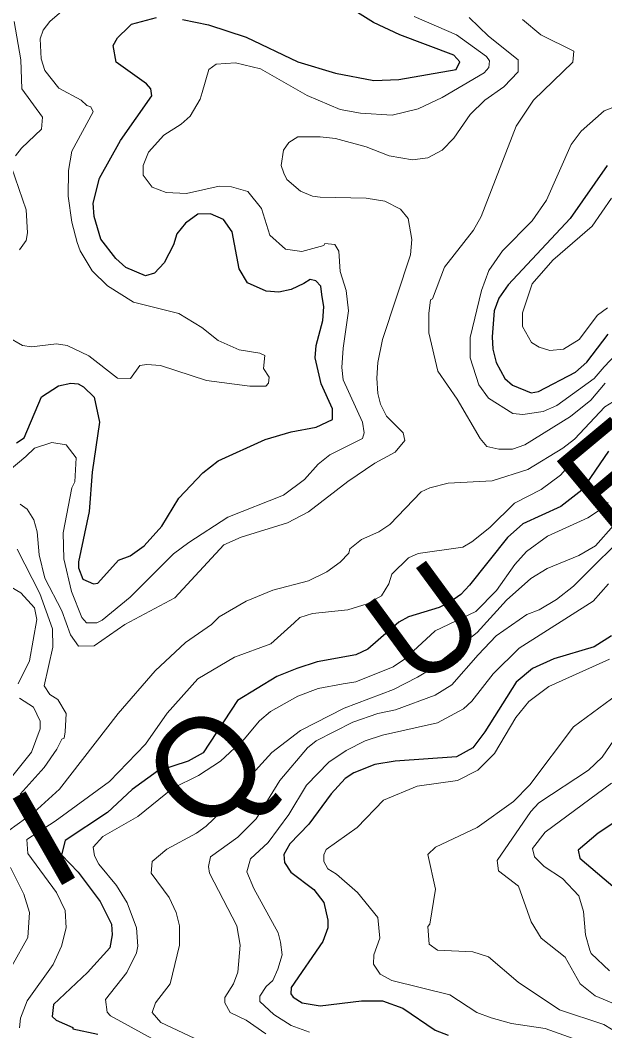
# Model space of a CAD drawing. Extents: x 423 to 448.8, y 7456.3 to 7484.
# Drawn here: x 431.771 to 432.712, y 7469.783 to 7471.409 of the extents above; entities that cross this region are included whole.
import ezdxf
from ezdxf.enums import TextEntityAlignment as Align

# ---------------------------------------------------------------- set-up
doc = ezdxf.new("R2010")
doc.units = 0
doc.header["$LTSCALE"] = 0.032
doc.layers.add('1', color=7, linetype='Continuous', lineweight=25)
doc.layers.add('2', color=7, linetype='Continuous', lineweight=13)
doc.layers.add('61', color=7, linetype='Continuous')

msp = doc.modelspace()

# ---------------------------------------------------------------- linework, layer by layer
at = {"layer": '1'}
for points in [[(432.0325, 7471.4102), (432.0743, 7471.4017), (432.1346, 7471.3815), (432.2181, 7471.3421), (432.2785, 7471.3236), (432.3404, 7471.3119), (432.3806, 7471.3135), (432.4726, 7471.3297), (432.4788, 7471.3421), (432.4687, 7471.3529), (432.3821, 7471.3854), (432.3396, 7471.4055), (432.3009, 7471.4295)], [(431.7657, 7470.7288), (431.778, 7470.7372), (431.8059, 7470.803), (431.833, 7470.8208), (431.8531, 7470.8247), (431.8646, 7470.8239), (431.8732, 7470.8193), (431.8902, 7470.8022), (431.8987, 7470.762), (431.8871, 7470.6816), (431.8825, 7470.6182), (431.8654, 7470.5377), (431.8654, 7470.5277), (431.8724, 7470.5098), (431.8894, 7470.5021), (431.8963, 7470.5029), (431.9296, 7470.54), (431.9482, 7470.547), (431.9706, 7470.5632), (431.9992, 7470.595), (432.0263, 7470.6398), (432.065, 7470.6808), (432.0897, 7470.7002), (432.1656, 7470.7342), (432.2073, 7470.7466), (432.2475, 7470.7543), (432.2738, 7470.7666), (432.2738, 7470.7837), (432.2553, 7470.8239), (432.246, 7470.8657), (432.2475, 7470.8858), (432.2584, 7470.926), (432.2599, 7470.9477), (432.2568, 7470.9678), (432.2552, 7470.9808), (432.2471, 7470.9896), (432.238, 7470.9917), (432.2274, 7470.9855), (432.2073, 7470.9755), (432.1872, 7470.9716), (432.1671, 7470.9732), (432.1369, 7470.9863), (432.1238, 7471.0088), (432.1121, 7471.0683), (432.0982, 7471.0884), (432.0774, 7471.0977), (432.0573, 7471.0969), (432.0372, 7471.0822), (432.0232, 7471.0652), (432.0178, 7471.0474), (432.0031, 7471.0188), (431.9876, 7471.0018), (431.9729, 7470.9979), (431.9412, 7471.0111), (431.925, 7471.0258), (431.901, 7471.0567), (431.8902, 7471.0931), (431.8886, 7471.1147), (431.8987, 7471.155), (431.9327, 7471.2153), (431.983, 7471.2872), (431.9815, 7471.2988), (431.9745, 7471.3066), (431.9257, 7471.3413), (431.9211, 7471.3684), (431.9281, 7471.3808), (431.9459, 7471.3986), (431.9505, 7471.4024), (431.9908, 7471.4133)], [(432.7155, 7471.175), (432.6559, 7471.0899), (432.5561, 7470.9832), (432.5414, 7470.9616), (432.5337, 7470.9415), (432.5306, 7470.8997), (432.5314, 7470.8796), (432.5368, 7470.858), (432.5507, 7470.8324), (432.5631, 7470.8216), (432.5933, 7470.8092), (432.6049, 7470.8115), (432.6644, 7470.8424), (432.683, 7470.8587), (432.717, 7470.9036)], [(432.7178, 7470.7156), (432.6745, 7470.653), (432.6412, 7470.6267), (432.5801, 7470.5988), (432.5553, 7470.5764), (432.4942, 7470.4998), (432.4803, 7470.4851), (432.4626, 7470.4728), (432.4455, 7470.4642), (432.396, 7470.4488), (432.3806, 7470.4402), (432.3303, 7470.397), (432.311, 7470.3877), (432.2491, 7470.3768), (432.2166, 7470.366), (432.1841, 7470.3528), (432.1207, 7470.3142), (432.0658, 7470.2299), (432.0418, 7470.2167), (431.9923, 7470.2005), (431.9513, 7470.1711), (431.9118, 7470.134), (431.8438, 7470.0891), (431.8376, 7470.0659), (431.8646, 7470.038), (431.9002, 7469.9909), (431.918, 7469.9545), (431.9196, 7469.9375), (431.9157, 7469.9166), (431.8794, 7469.8764), (431.8252, 7469.8254), (431.8229, 7469.806), (431.8291, 7469.7999), (431.8561, 7469.7882), (431.8561, 7469.7859), (431.8964, 7469.7774)], [(432.7224, 7470.4186), (432.6946, 7470.4008), (432.6296, 7470.3815), (432.5956, 7470.366), (432.5693, 7470.3436), (432.519, 7470.2639), (432.4997, 7470.2384), (432.4734, 7470.2237), (432.3744, 7470.2167), (432.3419, 7470.2113), (432.3079, 7470.1982), (432.2939, 7470.1889), (432.2715, 7470.1641), (432.2359, 7470.1154), (432.205, 7470.0837), (432.1957, 7470.0667), (432.1965, 7470.0536), (432.2065, 7470.038), (432.2437, 7470.0102), (432.2599, 7469.9893), (432.2661, 7469.9607), (432.2661, 7469.9483), (432.2584, 7469.9267), (432.2073, 7469.8524), (432.2065, 7469.8424), (432.2104, 7469.837), (432.2251, 7469.8277), (432.2537, 7469.823), (432.3202, 7469.8308), (432.3543, 7469.8308), (432.3868, 7469.8192), (432.4386, 7469.7836), (432.4595, 7469.7759)], [(432.7851, 7470.1564), (432.7008, 7470.1007), (432.6691, 7470.0736), (432.6714, 7470.0605), (432.7286, 7470.0125)]]:
    msp.add_lwpolyline(points, dxfattribs=at)
at = {"layer": '2'}
for points in [[(431.7509, 7470.8997), (431.7749, 7470.8858), (431.7897, 7470.8834), (431.8299, 7470.8881), (431.8469, 7470.8858), (431.8817, 7470.8687), (431.9281, 7470.8332), (431.949, 7470.8324), (431.9637, 7470.8533), (431.9753, 7470.8549), (431.9969, 7470.8533), (432.0712, 7470.8293), (432.1408, 7470.82), (432.1663, 7470.82), (432.1709, 7470.8247), (432.1717, 7470.8347), (432.1625, 7470.8486), (432.1648, 7470.8695), (432.157, 7470.8734), (432.1238, 7470.8788), (432.0898, 7470.8935), (432.0635, 7470.9144), (432.0263, 7470.9368), (431.9536, 7470.9554), (431.9119, 7470.9817), (431.8871, 7471.0057), (431.8677, 7471.0381), (431.8631, 7471.0513), (431.8546, 7471.0838), (431.8484, 7471.1256), (431.8492, 7471.1673), (431.8546, 7471.1983), (431.8886, 7471.2617), (431.8848, 7471.2694), (431.8786, 7471.2717), (431.8693, 7471.2803), (431.8337, 7471.2996), (431.8113, 7471.3282), (431.8051, 7471.3468), (431.8036, 7471.3793), (431.8082, 7471.3931), (431.819, 7471.4071), (431.8383, 7471.4233)], [(431.7711, 7470.6305), (431.7827, 7470.622), (431.7935, 7470.605), (431.7989, 7470.5857), (431.802, 7470.5486), (431.8113, 7470.5114), (431.8383, 7470.4588), (431.8523, 7470.4202), (431.8654, 7470.4016), (431.8902, 7470.4023), (431.9397, 7470.4364), (432.0201, 7470.4797), (432.099, 7470.5648), (432.1269, 7470.5772), (432.2011, 7470.6004), (432.2351, 7470.6181), (432.2985, 7470.6669), (432.3419, 7470.6963), (432.3744, 7470.714), (432.3899, 7470.7326), (432.3875, 7470.745), (432.3605, 7470.7721), (432.3511, 7470.7912), (432.3465, 7470.8084), (432.345, 7470.8332), (432.3465, 7470.858), (432.3543, 7470.8951), (432.3991, 7471.0312), (432.4014, 7471.056), (432.3952, 7471.0899), (432.3829, 7471.1047), (432.3581, 7471.1178), (432.328, 7471.1225), (432.2537, 7471.124), (432.2414, 7471.1256), (432.222, 7471.134), (432.2003, 7471.1526), (432.1957, 7471.1627), (432.191, 7471.1751), (432.1949, 7471.1998), (432.2034, 7471.2122), (432.2181, 7471.2215), (432.2537, 7471.2215), (432.2785, 7471.2184), (432.328, 7471.2052), (432.3651, 7471.1905), (432.4022, 7471.1843), (432.427, 7471.1874), (432.4501, 7471.1998), (432.4687, 7471.2191), (432.495, 7471.2571), (432.519, 7471.2803), (432.5492, 7471.3019), (432.5724, 7471.3259), (432.5724, 7471.3452), (432.5244, 7471.3831), (432.4935, 7471.4132)], [(432.0448, 7471.2547), (432.0611, 7471.2818), (432.0642, 7471.2926), (432.075, 7471.3298), (432.0867, 7471.3382), (432.1176, 7471.3406), (432.1578, 7471.3305), (432.2328, 7471.288), (432.2862, 7471.2655), (432.3187, 7471.2593), (432.3697, 7471.2563), (432.4115, 7471.2663), (432.4502, 7471.2849), (432.5175, 7471.3243), (432.5252, 7471.3328), (432.526, 7471.3437), (432.5213, 7471.3506), (432.4733, 7471.3854), (432.4053, 7471.4148)], [(431.7641, 7471.1905), (431.7734, 7471.2029), (431.8059, 7471.2338), (431.8074, 7471.2532), (431.7741, 7471.2988), (431.7726, 7471.3452), (431.7618, 7471.4071)], [(432.5793, 7471.4102), (432.6087, 7471.3854), (432.6621, 7471.3591), (432.6605, 7471.3413), (432.5971, 7471.2802), (432.5693, 7471.2385), (432.5128, 7471.0931), (432.5004, 7471.0714), (432.454, 7471.0118), (432.4347, 7470.9608), (432.4316, 7470.9592), (432.4285, 7470.9368), (432.4285, 7470.9059), (432.4432, 7470.844), (432.4742, 7470.7992)], [(432.7294, 7470.8711), (432.7108, 7470.851), (432.6946, 7470.8324), (432.6343, 7470.7891), (432.6126, 7470.7791), (432.5801, 7470.7744), (432.5639, 7470.7759), (432.5244, 7470.8007), (432.5089, 7470.8224), (432.495, 7470.8657), (432.495, 7470.8982), (432.5136, 7470.974), (432.5252, 7471.0065), (432.5469, 7471.0381), (432.5948, 7471.0861), (432.618, 7471.1193), (432.6574, 7471.2091), (432.6737, 7471.2307), (432.7108, 7471.2632), (432.7426, 7471.2756)], [(431.7502, 7470.6816), (431.7804, 7470.7071), (431.7942, 7470.7203), (431.8221, 7470.7295), (431.8453, 7470.7257), (431.8616, 7470.7048), (431.8593, 7470.6661), (431.8546, 7470.6568), (431.8407, 7470.5841), (431.8414, 7470.5424), (431.8538, 7470.4898), (431.8708, 7470.448), (431.8778, 7470.4395), (431.8948, 7470.4395), (431.9033, 7470.4434), (431.9482, 7470.4805), (432.0178, 7470.5501), (432.0426, 7470.5687), (432.1052, 7470.6096), (432.1949, 7470.6445), (432.2289, 7470.67), (432.2506, 7470.6947), (432.2692, 7470.7094), (432.3218, 7470.7357), (432.3249, 7470.745), (432.3218, 7470.762), (432.2908, 7470.8301), (432.2885, 7470.8502), (432.2908, 7470.8812), (432.2993, 7470.9415), (432.2955, 7470.974), (432.2862, 7471.0049), (432.2839, 7471.0374), (432.2777, 7471.0482), (432.2614, 7471.0497), (432.2599, 7471.0466), (432.2243, 7471.0366), (432.198, 7471.0404), (432.1732, 7471.0629), (432.1594, 7471.1062), (432.1377, 7471.1333), (432.1114, 7471.141), (432.0913, 7471.1418), (432.0387, 7471.1302), (432.0062, 7471.1317), (431.9838, 7471.1402), (431.9691, 7471.1596), (431.9691, 7471.1751), (431.9776, 7471.1967), (432.0023, 7471.2238), (432.0302, 7471.2415), (432.0448, 7471.2547)], [(431.7703, 7471.0397), (431.7811, 7471.0544), (431.7834, 7471.0668), (431.7811, 7471.1039), (431.7572, 7471.1727)], [(432.7224, 7471.1224), (432.6915, 7471.0776), (432.6281, 7471.0227), (432.5948, 7470.9848), (432.5793, 7470.9384), (432.5793, 7470.9159), (432.594, 7470.8904), (432.6064, 7470.8827), (432.6234, 7470.8773), (432.6451, 7470.8796), (432.6706, 7470.8951), (432.7, 7470.9345), (432.7163, 7470.9461)], [(432.4742, 7470.7992), (432.5113, 7470.7357), (432.5221, 7470.7233), (432.5415, 7470.7187), (432.5631, 7470.7187), (432.5832, 7470.7257), (432.6567, 7470.7713), (432.6892, 7470.7976), (432.7124, 7470.8247)], [(432.7395, 7470.8038), (432.7116, 7470.7868), (432.6629, 7470.735), (432.6443, 7470.7203), (432.5879, 7470.6862), (432.5306, 7470.6677), (432.4595, 7470.6638), (432.4301, 7470.6568), (432.4162, 7470.6499), (432.3658, 7470.5973), (432.3481, 7470.5857), (432.3202, 7470.5733), (432.3016, 7470.5586), (432.3001, 7470.5516), (432.2862, 7470.5369), (432.2646, 7470.5215), (432.2352, 7470.5068), (432.1779, 7470.4921), (432.1346, 7470.4743), (432.0913, 7470.4488), (432.0789, 7470.4364), (432.0372, 7470.4078), (431.9884, 7470.3621), (431.9289, 7470.2933), (431.8345, 7470.1719), (431.7935, 7470.134), (431.7533, 7470.1053)], [(432.7286, 7470.7698), (432.6946, 7470.7388), (432.6405, 7470.677), (432.6095, 7470.6537), (432.5662, 7470.6321), (432.5267, 7470.5926), (432.4981, 7470.5694), (432.4834, 7470.5609), (432.4115, 7470.5509)], [(432.717, 7470.6328), (432.7031, 7470.6205), (432.6845, 7470.6081), (432.6195, 7470.5787), (432.5855, 7470.554), (432.5669, 7470.5331), (432.5376, 7470.4913), (432.5043, 7470.4573), (432.4386, 7470.4264), (432.3898, 7470.3807), (432.3713, 7470.3683), (432.311, 7470.3444), (432.2909, 7470.3413), (432.2506, 7470.3335), (432.2181, 7470.3211), (432.174, 7470.2964), (432.1562, 7470.2817), (432.1315, 7470.2523), (432.0936, 7470.2167), (432.058, 7470.1935), (432.017, 7470.1734), (431.9606, 7470.1278), (431.9041, 7470.0953), (431.8886, 7470.0783), (431.8909, 7470.0644), (431.8979, 7470.0512), (431.9265, 7470.0164), (431.9435, 7469.9886), (431.9583, 7469.9484), (431.9606, 7469.919), (431.9583, 7469.9081), (431.9428, 7469.8764), (431.9087, 7469.8331), (431.9111, 7469.813), (431.9165, 7469.8068), (431.983, 7469.7704)], [(432.7557, 7470.6298), (432.6969, 7470.5632), (432.6699, 7470.5478), (432.6188, 7470.5269), (432.5925, 7470.5106), (432.5538, 7470.4759), (432.5066, 7470.424), (432.4293, 7470.3629)], [(432.7596, 7470.5957), (432.6613, 7470.4983), (432.6342, 7470.4766), (432.6064, 7470.4604), (432.5863, 7470.4526), (432.5368, 7470.4186), (432.5082, 7470.3877), (432.4657, 7470.3397), (432.4386, 7470.3227), (432.3751, 7470.2995), (432.3465, 7470.2933), (432.3063, 7470.2794), (432.2475, 7470.2492), (432.2336, 7470.2384), (432.1888, 7470.1858), (432.1508, 7470.1239), (432.1214, 7470.0945), (432.0774, 7470.0628), (432.0743, 7470.0474), (432.0758, 7470.0365), (432.1199, 7469.9515), (432.1253, 7469.9205), (432.1214, 7469.8772), (432.1145, 7469.8586), (432.1006, 7469.8362), (432.1006, 7469.8277), (432.1091, 7469.8122), (432.1346, 7469.7999), (432.1663, 7469.7782)], [(431.7664, 7470.5578), (431.8028, 7470.4867), (431.8236, 7470.4295), (431.8237, 7470.4001), (431.8098, 7470.3381), (431.819, 7470.3242), (431.8322, 7470.3157), (431.8453, 7470.2933), (431.8438, 7470.2639), (431.8422, 7470.2539), (431.8383, 7470.2523), (431.8306, 7470.2361), (431.8097, 7470.2067), (431.7711, 7470.1634)], [(432.4115, 7470.5509), (432.396, 7470.5439), (432.3689, 7470.5176), (432.3643, 7470.5022), (432.3527, 7470.4828), (432.3295, 7470.4697), (432.2986, 7470.4604), (432.2414, 7470.4542), (432.2212, 7470.448), (432.212, 7470.4395), (432.1748, 7470.4054), (432.1161, 7470.3838), (432.0573, 7470.349), (432.0077, 7470.2941), (431.9729, 7470.2438), (431.9149, 7470.1842), (431.8275, 7470.12), (431.7819, 7470.0907), (431.7835, 7470.0682), (431.8298, 7470.0056), (431.8438, 7469.9762), (431.8453, 7469.9484), (431.8376, 7469.919), (431.8244, 7469.8896), (431.7827, 7469.8308), (431.7718, 7469.803), (431.7703, 7469.7875)], [(431.7479, 7470.5021), (431.7726, 7470.4874), (431.7943, 7470.4635), (431.7981, 7470.4449), (431.7866, 7470.3784), (431.768, 7470.3413)], [(432.157, 7469.83), (432.157, 7469.8385), (432.1671, 7469.854), (432.1779, 7469.864), (432.1856, 7469.8818), (432.1926, 7469.905), (432.1903, 7469.9252), (432.1864, 7469.9406), (432.147, 7470.0118), (432.1362, 7470.0388), (432.1416, 7470.0597), (432.1702, 7470.086), (432.2034, 7470.1309), (432.2321, 7470.1781), (432.2677, 7470.2152), (432.2955, 7470.2337), (432.3264, 7470.2492), (432.3543, 7470.2585), (432.4425, 7470.2786), (432.4842, 7470.301), (432.4981, 7470.3134), (432.5321, 7470.3575), (432.5739, 7470.3985), (432.693, 7470.4743), (432.7178, 7470.5022)], [(432.7194, 7470.3807), (432.6219, 7470.3366), (432.5894, 7470.3126), (432.5685, 7470.2871), (432.5345, 7470.2291), (432.5074, 7470.202), (432.4749, 7470.1858), (432.41, 7470.1765), (432.3558, 7470.1541), (432.3133, 7470.11), (432.2638, 7470.0744), (432.2599, 7470.0659), (432.2599, 7470.0551), (432.2661, 7470.0435), (432.28, 7470.0349), (432.3141, 7470.0056), (432.3465, 7469.9653), (432.3496, 7469.9321), (432.3403, 7469.905), (432.3395, 7469.8903), (432.3504, 7469.8741), (432.3689, 7469.864), (432.4626, 7469.8408), (432.5059, 7469.8122), (432.5291, 7469.8037), (432.5616, 7469.7944), (432.6157, 7469.7867), (432.6606, 7469.7705)], [(432.4293, 7470.3629), (432.4107, 7470.3521), (432.372, 7470.332), (432.2924, 7470.3018), (432.222, 7470.2662), (432.1763, 7470.2306), (432.1338, 7470.1842), (432.0936, 7470.134), (432.0704, 7470.1123), (432.0549, 7470.1007), (432.007, 7470.0752), (431.9838, 7470.0551), (431.9822, 7470.0365), (432.0109, 7469.9971), (432.0224, 7469.9731), (432.0279, 7469.9515), (432.0279, 7469.9205), (432.0124, 7469.8586), (431.9892, 7469.8277), (431.9838, 7469.8122), (431.9977, 7469.796), (432.0511, 7469.7712)], [(432.7325, 7470.3243), (432.6613, 7470.2717), (432.591, 7470.1788), (432.5647, 7470.1518), (432.5066, 7470.11), (432.4394, 7470.0783), (432.427, 7470.0667), (432.4394, 7470.011), (432.4301, 7469.9545), (432.427, 7469.9507), (432.4293, 7469.9221), (432.4425, 7469.9127), (432.4997, 7469.9097), (432.5244, 7469.9019)], [(431.7703, 7470.318), (431.7927, 7470.3034), (431.8036, 7470.2809), (431.8036, 7470.2686), (431.7896, 7470.2314), (431.7595, 7470.1935)], [(432.7441, 7470.2763), (432.7077, 7470.2229), (432.6853, 7470.2021), (432.6056, 7470.1494), (432.5925, 7470.1355), (432.5384, 7470.0566), (432.5407, 7470.0404), (432.5731, 7470.0156), (432.5932, 7469.9584), (432.6095, 7469.9321), (432.6482, 7469.9012), (432.6721, 7469.8586), (432.6961, 7469.8393), (432.7255, 7469.8269)], [(432.7224, 7470.1812), (432.6157, 7470.1023), (432.5956, 7470.076), (432.5987, 7470.0628), (432.6142, 7470.0474), (432.6436, 7470.028), (432.6698, 7470.0002), (432.6776, 7469.9747), (432.6807, 7469.9375), (432.6876, 7469.9128), (432.6899, 7469.9073), (432.7193, 7469.8795)], [(431.7556, 7470.0458), (431.7773, 7470.0025), (431.7866, 7469.9731), (431.7835, 7469.9328), (431.7587, 7469.888)], [(432.5244, 7469.9019), (432.5723, 7469.8609), (432.6389, 7469.8168), (432.71, 7469.7929), (432.7472, 7469.7705)], [(432.2367, 7469.7805), (432.2073, 7469.7913), (432.1795, 7469.8091), (432.157, 7469.83)]]:
    msp.add_lwpolyline(points, dxfattribs=at)

# ---------------------------------------------------------------- texts
at = {"layer": '61'}
for s, rotation, p in [('E', 39.833, (432.7783, 7470.6109)), ('U', 36.249, (432.4697, 7470.3742)), ('Q', 42.492, (432.1241, 7470.1486))]:
    msp.add_text(s, height=0.16, rotation=rotation, dxfattribs=at).set_placement(p, align=Align.CENTER)
at = {"layer": '61', "width": 1.2}
msp.add_text('I', height=0.16, rotation=29.776, dxfattribs=at).set_placement((431.8492, 7470.0233), align=Align.CENTER)

doc.saveas('drawing.dxf')
